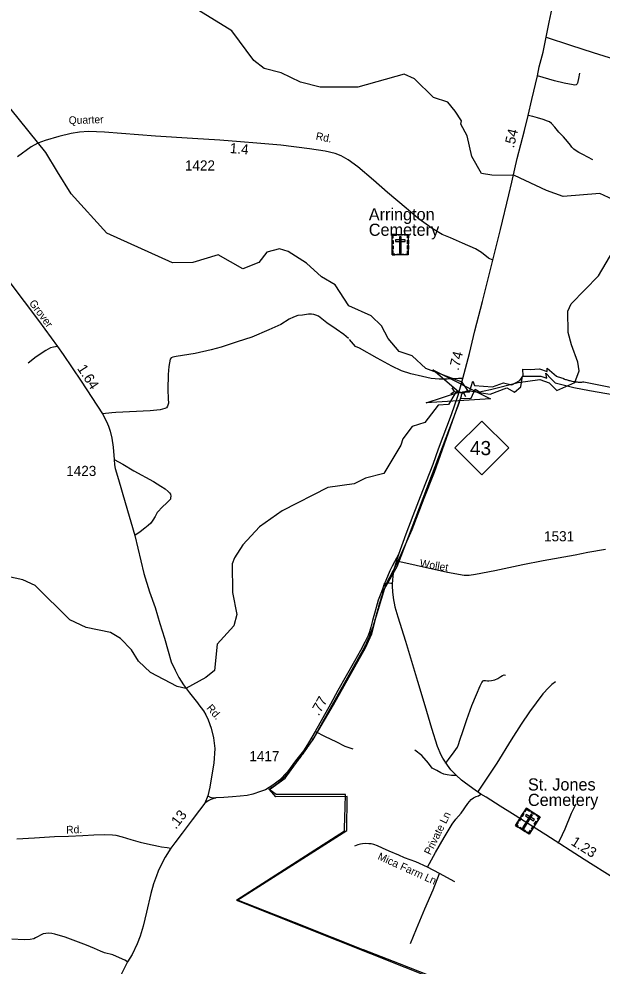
# Model space of a CAD drawing. Extents: x 2220236 to 2384410, y 720751 to 894131.
# Drawn here: x 2309628 to 2316835, y 842180 to 853889 of the extents above; entities that cross this region are included whole.
import ezdxf

# ---------------------------------------------------------------- set-up
doc = ezdxf.new("R2010")
doc.units = 0
doc.layers.add('Default', color=7, linetype='Continuous')

msp = doc.modelspace()

# ---------------------------------------------------------------- linework, layer by layer
at = {"layer": 'Default'}
for p, q in [((2314979, 849327), (2315007, 849285)), ((2314965, 849255), (2315007, 849285)), ((2315007, 849285), (2315125, 849261)), ((2315167, 849291), (2315125, 849261)), ((2315153, 849219), (2315125, 849261)), ((2314825, 843322), (2314676, 843403)), ((2315016, 843220), (2314825, 843322))]:
    msp.add_line(p, q, dxfattribs=at)
for points in [[(2316145, 853665), (2316183, 853850), (2316205, 853964), (2316226, 854081), (2316235, 854178), (2316238, 854273), (2316240, 854418), (2316238, 854579), (2316233, 854745), (2316224, 855064), (2316192, 855549), (2316193, 855755), (2316188, 855798)], [(2310106, 851999), (2309962, 852239), (2309531, 852769), (2309363, 852933), (2309057, 853505), (2308871, 853694), (2308704, 853819), (2308561, 853882), (2308119, 853913), (2308019, 853978), (2307934, 854066), (2307925, 854125), (2307799, 854284), (2307595, 854623), (2307342, 854918)], [(2317074, 851608), (2316806, 851732), (2316356, 851694), (2316147, 851767), (2315754, 851954), (2315471, 851959), (2315345, 851980), (2315227, 852189), (2315166, 852446), (2315089, 852587), (2315097, 852630), (2315021, 852751), (2314928, 852859), (2314752, 852918), (2314517, 853148), (2314391, 853205), (2313818, 853047), (2313352, 853044), (2313109, 853106), (2312867, 853221), (2312658, 853278), (2312532, 853375), (2312261, 853741), (2311850, 853994)], [(2315485, 850905), (2315579, 851285), (2315684, 851714), (2315720, 851871), (2315787, 852162), (2315877, 852509), (2315921, 852695), (2315969, 852895), (2316035, 853186), (2316059, 853297), (2316108, 853478), (2316145, 853665)], [(2316145, 853665), (2316445, 853567), (2316726, 853473), (2316988, 853393), (2317156, 853343), (2317317, 853308), (2317485, 853272), (2317630, 853225), (2317721, 853192), (2317809, 853152), (2317905, 853096), (2317993, 853031)], [(2316558, 853219), (2316543, 853154), (2316535, 853114), (2316530, 853096), (2316527, 853086), (2316522, 853081), (2316513, 853076), (2316498, 853069), (2316477, 853074), (2316367, 853097), (2316248, 853126), (2316108, 853167), (2316035, 853186)], [(2316722, 852147), (2316660, 852181), (2316597, 852214), (2316546, 852239), (2316514, 852260), (2316486, 852279), (2316463, 852305), (2316444, 852330), (2316406, 852375), (2316357, 852431), (2316302, 852491), (2316252, 852551), (2316210, 852596), (2316187, 852616), (2316162, 852626), (2316109, 852644), (2316035, 852667), (2315981, 852684), (2315921, 852695)], [(2315485, 850905), (2315431, 850932), (2315345, 851003), (2315272, 851048), (2315108, 851119), (2314961, 851181), (2314860, 851226), (2314734, 851297), (2314560, 851425), (2314415, 851549), (2314183, 851745), (2314012, 851898), (2313816, 852059), (2313697, 852147), (2313612, 852197), (2313537, 852225), (2313413, 852254), (2313219, 852285), (2312864, 852327), (2312567, 852353), (2312366, 852368), (2312109, 852390), (2311773, 852410), (2311316, 852441), (2310686, 852491), (2310489, 852496), (2310376, 852491), (2310273, 852471), (2310120, 852436), (2309953, 852387), (2309862, 852352), (2309779, 852307), (2309608, 852184)], [(2315177, 849296), (2315107, 849397), (2314655, 849566), (2314487, 849723), (2314328, 849779), (2314193, 849938), (2314108, 850095), (2313982, 850218), (2313705, 850341), (2313536, 850603), (2313368, 850701), (2313183, 850868), (2312957, 851016), (2312848, 851048), (2312690, 851005), (2312592, 850876), (2312393, 850799), (2312091, 850971), (2311776, 850876), (2311525, 850875), (2310714, 851239), (2310275, 851727), (2310106, 851999)], [(2315177, 849296), (2315300, 849275), (2315457, 849309), (2315798, 849396), (2316064, 849433), (2316181, 849392), (2316274, 849294), (2316498, 849395), (2316554, 849539), (2316537, 849646), (2316459, 849860), (2316416, 850012), (2316413, 850278), (2316454, 850368), (2316792, 850714), (2316980, 851033), (2317033, 851485), (2317074, 851608)], [(2314297, 847190), (2314325, 847272), (2314413, 847525), (2314502, 847751), (2314618, 848059), (2314746, 848384), (2314814, 848573), (2314976, 848997), (2315057, 849236), (2315113, 849442), (2315195, 849753), (2315264, 850033), (2315356, 850397), (2315485, 850905)], [(2309515, 850631), (2309868, 850159), (2310103, 849839), (2310174, 849742), (2310396, 849409), (2310660, 849007), (2310708, 848912), (2310734, 848856), (2310756, 848793), (2310777, 848708), (2310792, 848593), (2310804, 848442), (2310807, 848378), (2310817, 848332), (2310859, 848196), (2310940, 847909), (2311060, 847501), (2311170, 847034), (2311241, 846805), (2311312, 846614), (2311371, 846413), (2311425, 846235), (2311474, 846071), (2311509, 845941), (2311557, 845836), (2311604, 845747), (2311662, 845655), (2311735, 845557), (2311836, 845436), (2311852, 845410), (2311907, 845335), (2311937, 845287), (2311966, 845222), (2312003, 845122), (2312033, 845003), (2312049, 844871), (2312035, 844690), (2312007, 844518), (2311989, 844391), (2311962, 844285), (2311926, 844194)], [(2313703, 849937), (2313643, 849987), (2313547, 850055), (2313435, 850134), (2313331, 850213), (2313299, 850228), (2313273, 850236), (2313244, 850239), (2313205, 850239), (2313132, 850228), (2313074, 850221), (2313022, 850201), (2312969, 850178), (2312866, 850113), (2312717, 850045), (2312506, 849955), (2312325, 849897), (2312128, 849831), (2312004, 849799), (2311806, 849753), (2311651, 849729), (2311573, 849716), (2311530, 849706), (2311510, 849699), (2311498, 849683), (2311479, 849591), (2311472, 849492), (2311470, 849309), (2311474, 849193), (2311475, 849140), (2311464, 849103), (2311450, 849082), (2311430, 849072), (2311373, 849056), (2311249, 849046), (2310824, 849024), (2310774, 849019), (2310660, 849007)], [(2315113, 849442), (2315060, 849442), (2314979, 849439), (2314919, 849434), (2314823, 849434), (2314723, 849444), (2314614, 849469), (2314470, 849503), (2314357, 849540), (2314238, 849596), (2314055, 849694), (2313835, 849819), (2313786, 849839), (2313713, 849924)], [(2310103, 849839), (2310055, 849831), (2310019, 849823), (2309960, 849792), (2309839, 849711), (2309742, 849634)], [(2315200, 841864), (2314330, 842207), (2313887, 842382), (2313884, 842382), (2313500, 842534), (2313149, 842672), (2312320, 842999), (2313650, 843853), (2313650, 843882), (2313650, 843884), (2313659, 844145), (2313664, 844302), (2312980, 844300), (2312805, 844299), (2312716, 844366), (2312725, 844372), (2312735, 844378), (2312745, 844384), (2312755, 844390), (2312764, 844396), (2312774, 844403), (2312784, 844409), (2312793, 844416), (2312802, 844423), (2312812, 844430), (2312821, 844437), (2312830, 844444), (2312838, 844452), (2312847, 844459), (2312856, 844467), (2312864, 844475), (2312873, 844483), (2312881, 844491), (2312890, 844499), (2312898, 844508), (2312902, 844512), (2312906, 844516), (2312913, 844525), (2312921, 844533), (2312929, 844543), (2312937, 844552), (2312945, 844560), (2312952, 844569), (2312960, 844578), (2312968, 844586), (2312975, 844595), (2312983, 844604), (2312990, 844613), (2312998, 844622), (2313005, 844631), (2313012, 844640), (2313020, 844649), (2313027, 844658), (2313034, 844667), (2313042, 844676), (2313049, 844685), (2313056, 844694), (2313064, 844703), (2313070, 844712), (2313078, 844721), (2313085, 844730), (2313092, 844740), (2313099, 844749), (2313106, 844758), (2313113, 844767), (2313120, 844777), (2313126, 844786), (2313134, 844795), (2313140, 844805), (2313147, 844814), (2313154, 844824), (2313160, 844833), (2313167, 844842), (2313174, 844852), (2313180, 844862), (2313187, 844871), (2313194, 844881), (2313200, 844890), (2313207, 844900), (2313213, 844909), (2313216, 844914), (2313220, 844919), (2313226, 844929), (2313232, 844938), (2313239, 844948), (2313245, 844958), (2313251, 844968), (2313258, 844978), (2313264, 844987), (2313270, 844997), (2313276, 845007), (2313282, 845017), (2313288, 845027), (2313294, 845037), (2313300, 845047), (2313306, 845057), (2313312, 845067), (2313318, 845077), (2313327, 845094), (2313882, 846088), (2313887, 846098), (2313892, 846108), (2313898, 846119), (2313903, 846130), (2313908, 846140), (2313913, 846150), (2313918, 846160), (2313923, 846171), (2313928, 846182), (2313932, 846192), (2313937, 846203), (2313942, 846213), (2313946, 846223), (2313946, 846224), (2313951, 846234), (2313956, 846245), (2313960, 846256), (2313968, 846277), (2313973, 846288), (2313977, 846299), (2313981, 846310), (2313985, 846321), (2313989, 846332), (2313993, 846343), (2313997, 846354), (2314001, 846364), (2314005, 846375), (2314008, 846386), (2314012, 846397), (2314016, 846408), (2314019, 846420), (2314022, 846431), (2314026, 846442), (2314032, 846464), (2314036, 846475), (2314039, 846486), (2314042, 846497), (2314045, 846509), (2314048, 846520), (2314053, 846540), (2314056, 846551), (2314058, 846562), (2314062, 846574), (2314064, 846585), (2314068, 846596), (2314070, 846607), (2314074, 846618), (2314077, 846630), (2314080, 846641), (2314083, 846652), (2314086, 846663), (2314096, 846696), (2314100, 846708), (2314103, 846719), (2314106, 846730), (2314110, 846741), (2314113, 846752), (2314116, 846763), (2314120, 846774), (2314124, 846785), (2314127, 846796), (2314130, 846807), (2314134, 846818), (2314138, 846829), (2314144, 846842), (2314303, 847119), (2314352, 847247), (2314999, 848954), (2315003, 848965), (2315008, 848976), (2315012, 848987), (2315016, 848997), (2315020, 849008), (2315024, 849019), (2315028, 849030), (2315032, 849041), (2315036, 849052), (2315040, 849063), (2315044, 849074), (2315048, 849084), (2315052, 849095), (2315056, 849106), (2315060, 849117), (2315071, 849150), (2315074, 849161), (2315078, 849172), (2315082, 849183), (2315085, 849194), (2315089, 849205), (2315092, 849216), (2315096, 849228), (2315099, 849239), (2315109, 849272), (2315110, 849277), (2315195, 849277), (2315238, 849409), (2315258, 849358), (2315481, 849341), (2315616, 849392), (2315720, 849367), (2315819, 849419), (2315858, 849476), (2315856, 849559), (2315946, 849557), (2316061, 849563), (2316158, 849531), (2316158, 849571), (2316270, 849472), (2316282, 849468), (2316361, 849442), (2316359, 849440), (2316382, 849433), (2316393, 849430), (2316404, 849427), (2316415, 849424), (2316426, 849420), (2316438, 849418), (2316449, 849415), (2316460, 849412), (2316482, 849407), (2316494, 849405), (2316506, 849403), (2316517, 849402), (2316528, 849401), (2316540, 849400), (2316552, 849399), (2316563, 849399), (2316575, 849399), (2316586, 849400), (2316598, 849401), (2316610, 849402), (2316611, 849402), (2317727, 849181)], [(2315200, 841864), (2314330, 842207), (2313887, 842382), (2313884, 842382), (2313500, 842534), (2313149, 842672), (2312320, 842999), (2313650, 843853), (2313650, 843882), (2313650, 843884), (2313659, 844145), (2313664, 844302), (2312980, 844300), (2312805, 844299), (2312716, 844366), (2312725, 844372), (2312735, 844378), (2312745, 844384), (2312755, 844390), (2312764, 844396), (2312774, 844403), (2312784, 844409), (2312793, 844416), (2312802, 844423), (2312812, 844430), (2312821, 844437), (2312830, 844444), (2312838, 844452), (2312847, 844459), (2312856, 844467), (2312864, 844475), (2312873, 844483), (2312881, 844491), (2312890, 844499), (2312898, 844508), (2312902, 844512), (2312906, 844516), (2312913, 844525), (2312921, 844533), (2312929, 844543), (2312937, 844552), (2312945, 844560), (2312952, 844569), (2312960, 844578), (2312968, 844586), (2312975, 844595), (2312983, 844604), (2312990, 844613), (2312998, 844622), (2313005, 844631), (2313012, 844640), (2313020, 844649), (2313027, 844658), (2313034, 844667), (2313042, 844676), (2313049, 844685), (2313056, 844694), (2313064, 844703), (2313070, 844712), (2313078, 844721), (2313085, 844730), (2313092, 844740), (2313099, 844749), (2313106, 844758), (2313113, 844767), (2313120, 844777), (2313126, 844786), (2313134, 844795), (2313140, 844805), (2313147, 844814), (2313154, 844824), (2313160, 844833), (2313167, 844842), (2313174, 844852), (2313180, 844862), (2313187, 844871), (2313194, 844881), (2313200, 844890), (2313207, 844900), (2313213, 844909), (2313216, 844914), (2313220, 844919), (2313226, 844929), (2313232, 844938), (2313239, 844948), (2313245, 844958), (2313251, 844968), (2313258, 844978), (2313264, 844987), (2313270, 844997), (2313276, 845007), (2313282, 845017), (2313288, 845027), (2313294, 845037), (2313300, 845047), (2313306, 845057), (2313312, 845067), (2313318, 845077), (2313327, 845094), (2313882, 846088), (2313887, 846098), (2313892, 846108), (2313898, 846119), (2313903, 846130), (2313908, 846140), (2313913, 846150), (2313918, 846160), (2313923, 846171), (2313928, 846182), (2313932, 846192), (2313937, 846203), (2313942, 846213), (2313946, 846223), (2313946, 846224), (2313951, 846234), (2313956, 846245), (2313960, 846256), (2313968, 846277), (2313973, 846288), (2313977, 846299), (2313981, 846310), (2313985, 846321), (2313989, 846332), (2313993, 846343), (2313997, 846354), (2314001, 846364), (2314005, 846375), (2314008, 846386), (2314012, 846397), (2314016, 846408), (2314019, 846420), (2314022, 846431), (2314026, 846442), (2314032, 846464), (2314036, 846475), (2314039, 846486), (2314042, 846497), (2314045, 846509), (2314048, 846520), (2314053, 846540), (2314056, 846551), (2314058, 846562), (2314062, 846574), (2314064, 846585), (2314068, 846596), (2314070, 846607), (2314074, 846618), (2314077, 846630), (2314080, 846641), (2314083, 846652), (2314086, 846663), (2314096, 846696), (2314100, 846708), (2314103, 846719), (2314106, 846730), (2314110, 846741), (2314113, 846752), (2314116, 846763), (2314120, 846774), (2314124, 846785), (2314127, 846796), (2314130, 846807), (2314134, 846818), (2314138, 846829), (2314144, 846842), (2314303, 847119), (2314352, 847247), (2314999, 848954), (2315003, 848965), (2315008, 848976), (2315012, 848987), (2315016, 848997), (2315020, 849008), (2315024, 849019), (2315028, 849030), (2315032, 849041), (2315036, 849052), (2315040, 849063), (2315044, 849074), (2315048, 849084), (2315052, 849095), (2315056, 849106), (2315060, 849117), (2315071, 849150), (2315074, 849161), (2315078, 849172), (2315082, 849183), (2315085, 849194), (2315089, 849205), (2315092, 849216), (2315096, 849228), (2315099, 849239), (2315109, 849272), (2315110, 849277), (2315195, 849277), (2315238, 849409), (2315258, 849358), (2315481, 849341), (2315616, 849392), (2315720, 849367), (2315819, 849419), (2315858, 849476), (2315856, 849559), (2315946, 849557), (2316061, 849563), (2316158, 849531), (2316158, 849571), (2316270, 849472), (2316282, 849468), (2316361, 849442), (2316359, 849440), (2316382, 849433), (2316393, 849430), (2316404, 849427), (2316415, 849424), (2316426, 849420), (2316438, 849418), (2316449, 849415), (2316460, 849412), (2316482, 849407), (2316494, 849405), (2316506, 849403), (2316517, 849402), (2316528, 849401), (2316540, 849400), (2316552, 849399), (2316563, 849399), (2316575, 849399), (2316586, 849400), (2316598, 849401), (2316610, 849402), (2316611, 849402), (2317727, 849181)], [(2315228, 841831), (2312322, 842991), (2313681, 843857), (2313686, 844275), (2312802, 844270), (2312725, 844363), (2312917, 844503), (2312994, 844607), (2313263, 844981), (2313516, 845410), (2313912, 846113), (2313988, 846289), (2314043, 846498), (2314163, 846891), (2314306, 847171), (2314487, 847578), (2314636, 847963), (2314762, 848287), (2315086, 849197), (2315218, 849202), (2315267, 849312), (2315339, 849268), (2315454, 849252), (2315657, 849329), (2315751, 849274), (2315833, 849340), (2315850, 849471), (2316080, 849471), (2316152, 849449), (2316141, 849510), (2316207, 849438), (2316256, 849389), (2316487, 849334), (2316679, 849296), (2317747, 849109)], [(2315177, 849296), (2315115, 849265), (2315066, 849273), (2315042, 849277), (2315027, 849271), (2315014, 849255), (2314938, 849124), (2314811, 849113), (2314646, 848899), (2314488, 848850), (2314373, 848698), (2314349, 848621), (2314136, 848271), (2313912, 848210), (2313771, 848141), (2313446, 848095), (2312883, 847806), (2312602, 847611), (2312396, 847386), (2312290, 847227), (2312265, 847151), (2312269, 846800), (2312322, 846526), (2312282, 846384), (2312076, 846159), (2312046, 845832), (2311939, 845749), (2311691, 845611), (2311582, 845636), (2311255, 845807), (2311104, 845948), (2311019, 846089), (2310884, 846228), (2310758, 846302), (2310458, 846365), (2310257, 846462), (2309828, 846884), (2309677, 846956), (2309485, 846994)], [(2310804, 848442), (2310913, 848383), (2311047, 848302), (2311289, 848171), (2311381, 848114), (2311434, 848078), (2311474, 848047), (2311488, 848031), (2311500, 848013), (2311505, 847989), (2311503, 847969), (2311499, 847951), (2311473, 847923), (2311446, 847899), (2311406, 847860), (2311337, 847788), (2311311, 847737), (2311282, 847691), (2311256, 847655), (2311225, 847627), (2311185, 847594), (2311128, 847549), (2311060, 847501)], [(2314297, 847190), (2314539, 847135), (2314926, 847051), (2315130, 847013), (2315191, 847013), (2315269, 847023), (2315509, 847070), (2315855, 847145), (2316109, 847193), (2316502, 847264), (2316660, 847295), (2316877, 847333)], [(2314138, 846884), (2314165, 846949), (2314218, 847070), (2314243, 847127), (2314275, 847181), (2314299, 847228), (2314325, 847272)], [(2314244, 846910), (2314250, 846947), (2314254, 847004), (2314267, 847085), (2314297, 847190)], [(2314244, 846910), (2314204, 846912), (2314184, 846914), (2314155, 846901), (2314138, 846884), (2314130, 846866), (2314108, 846806), (2314067, 846702), (2314032, 846567), (2313999, 846451), (2313976, 846370), (2313962, 846313), (2313943, 846265), (2313903, 846184), (2313849, 846081), (2313776, 845951), (2313570, 845588), (2313478, 845416), (2313287, 845080), (2313207, 844941), (2313144, 844840), (2313046, 844715), (2312949, 844581), (2312848, 844478), (2312765, 844415), (2312675, 844360), (2312613, 844338), (2312518, 844305), (2312447, 844290), (2312361, 844282), (2312269, 844273), (2312162, 844264), (2312062, 844258), (2311998, 844237), (2311967, 844223), (2311926, 844194)], [(2314139, 846908), (2314174, 846915), (2314190, 846917), (2314205, 846916), (2314225, 846912), (2314243, 846907)], [(2316979, 843267), (2316613, 843499), (2316141, 843800), (2315730, 844060), (2315576, 844156), (2315401, 844267), (2315337, 844304), (2315267, 844356), (2315149, 844440), (2315098, 844479), (2315030, 844540), (2314966, 844606), (2314924, 844665), (2314899, 844700), (2314868, 844748), (2314848, 844786), (2314802, 844893), (2314731, 845117), (2314647, 845398), (2314556, 845697), (2314408, 846191), (2314314, 846495), (2314279, 846617), (2314273, 846647), (2314260, 846708), (2314250, 846803), (2314245, 846880), (2314244, 846910)], [(2314901, 844684), (2314937, 844732), (2315006, 844827), (2315047, 844886), (2315062, 844920), (2315079, 844971), (2315117, 845091), (2315165, 845227), (2315225, 845403), (2315284, 845536), (2315329, 845645), (2315349, 845685), (2315364, 845707), (2315374, 845712), (2315394, 845710), (2315419, 845707), (2315434, 845707), (2315469, 845710), (2315508, 845718), (2315548, 845735), (2315583, 845758), (2315606, 845773), (2315625, 845780), (2315641, 845778)], [(2316260, 845694), (2316216, 845662), (2316177, 845625), (2316105, 845547), (2316022, 845433), (2315937, 845322), (2315835, 845169), (2315710, 844975), (2315535, 844689), (2315295, 844328)], [(2313759, 844863), (2313661, 844893), (2313548, 844953), (2313417, 845015), (2313287, 845080)], [(2315027, 844535), (2314974, 844535), (2314922, 844542), (2314881, 844552), (2314843, 844570), (2314792, 844596), (2314737, 844627), (2314690, 844686), (2314606, 844783), (2314521, 844848)], [(2311962, 844285), (2311993, 844269), (2312021, 844261), (2312062, 844258)], [(2314676, 843403), (2314778, 843584), (2314884, 843768), (2314981, 843933), (2315028, 843994), (2315093, 844069), (2315178, 844191), (2315218, 844237), (2315244, 844259), (2315281, 844276), (2315309, 844286), (2315337, 844304)], [(2311926, 844194), (2311861, 844108), (2311770, 843986), (2311644, 843823), (2311553, 843703), (2311504, 843637)], [(2316510, 844183), (2316453, 844066), (2316375, 843871), (2316310, 843733), (2316289, 843694)], [(2309600, 843754), (2309818, 843766), (2310068, 843782), (2310242, 843786), (2310416, 843792), (2310552, 843800), (2310689, 843806), (2310783, 843802), (2310826, 843796), (2310904, 843779), (2311011, 843746), (2311125, 843713), (2311215, 843691), (2311351, 843661), (2311391, 843655), (2311458, 843645), (2311504, 843637)], [(2314676, 843403), (2314534, 843470), (2314393, 843518), (2314322, 843552), (2314204, 843600), (2314121, 843639), (2314061, 843664), (2314013, 843681), (2313981, 843689), (2313954, 843691), (2313913, 843693), (2313875, 843692), (2313848, 843685), (2313817, 843677), (2313777, 843660)], [(2311504, 843637), (2311437, 843527), (2311390, 843441), (2311347, 843352), (2311326, 843296), (2311291, 843195), (2311257, 843075), (2311204, 842845), (2311163, 842674), (2311126, 842549), (2311089, 842456), (2311026, 842321), (2310968, 842231), (2310873, 842044)], [(2314466, 842458), (2314542, 842638), (2314644, 842885), (2314746, 843123), (2314825, 843322)], [(2310968, 842231), (2310935, 842251), (2310872, 842283), (2310788, 842318), (2310684, 842345), (2310634, 842362), (2310563, 842395), (2310463, 842438), (2310332, 842489), (2310198, 842535), (2310072, 842572), (2310033, 842582), (2309995, 842587), (2309962, 842583), (2309928, 842576), (2309834, 842527), (2309810, 842517), (2309768, 842507), (2309691, 842504), (2309540, 842510)]]:
    msp.add_lwpolyline(points, dxfattribs=at)
for points in [[(2314241, 851226), (2314440, 851226), (2314440, 850971), (2314241, 850971)], [(2314241, 851182), (2314253, 851182), (2314253, 851215), (2314293, 851215), (2314293, 851226), (2314241, 851226)], [(2314315, 851226), (2314367, 851226), (2314367, 851214), (2314315, 851214)], [(2314350, 851196), (2314332, 851196), (2314332, 850994), (2314350, 850994)], [(2314441, 851182), (2314429, 851182), (2314429, 851215), (2314389, 851215), (2314389, 851226), (2314441, 851226)], [(2314241, 851108), (2314241, 851152), (2314253, 851152), (2314253, 851108)], [(2314241, 851041), (2314241, 851084), (2314253, 851084), (2314253, 851041)], [(2314282, 851158), (2314282, 851139), (2314400, 851139), (2314400, 851158)], [(2314429, 851109), (2314429, 851153), (2314441, 851153), (2314441, 851109)], [(2314429, 851043), (2314429, 851087), (2314441, 851087), (2314441, 851043)], [(2314274, 850971), (2314274, 850983), (2314252, 850983), (2314252, 851023), (2314241, 851023), (2314241, 850971)], [(2314299, 850983), (2314384, 850983), (2314384, 850971), (2314299, 850971)], [(2314407, 850971), (2314407, 850983), (2314429, 850983), (2314429, 851023), (2314440, 851023), (2314440, 850971)], [(2314742, 849550), (2315458, 849193), (2314660, 849144), (2315066, 849273)], [(2315016, 848585), (2315349, 848918), (2315682, 848585), (2315349, 848252)], [(2315900, 844132), (2316068, 844026), (2315933, 843810), (2315764, 843916)], [(2315837, 844032), (2315860, 844069), (2315870, 844063), (2315847, 844026)], [(2315976, 844049), (2315960, 844059), (2315853, 843887), (2315869, 843877)], [(2315877, 844095), (2315886, 844089), (2315903, 844116), (2315938, 844095), (2315943, 844104), (2315900, 844132)], [(2315898, 844052), (2315888, 844037), (2315988, 843974), (2315998, 843990)], [(2315962, 844092), (2316006, 844065), (2316000, 844055), (2315956, 844083)], [(2316045, 843989), (2316036, 843995), (2316053, 844022), (2316018, 844044), (2316024, 844053), (2316068, 844026)], [(2315792, 843898), (2315798, 843908), (2315780, 843920), (2315801, 843954), (2315792, 843960), (2315764, 843916)], [(2315801, 843975), (2315824, 844012), (2315834, 844006), (2315811, 843969)], [(2315997, 843933), (2316020, 843970), (2316029, 843964), (2316006, 843927)], [(2315819, 843895), (2315891, 843850), (2315885, 843840), (2315813, 843886)], [(2315905, 843828), (2315911, 843838), (2315930, 843826), (2315951, 843860), (2315960, 843854), (2315933, 843810)], [(2315962, 843877), (2315985, 843914), (2315994, 843908), (2315971, 843871)]]:
    msp.add_lwpolyline(points, close=True, dxfattribs=at)

# ---------------------------------------------------------------- texts
for s, height, rotation, p in [('Quarter', 95, 1.6184, (2310244, 852589)), ('Rd.', 95, 348.9522, (2313291, 852398)), ('.54', 125, 76.3072, (2315744, 852287)), ('1.4', 125, 355.2152, (2312230, 852232)), ('Grover', 95, 306.7728, (2309748, 850374)), ('.74', 125, 76.034, (2315062, 849536)), ('1.64', 125, 303.0965, (2310343, 849568)), ('Wollet', 95, 350.6083, (2314577, 847117)), ('.77', 125, 60.1099, (2313332, 845265)), ('Rd.', 95, 310.7982, (2311940, 845366)), ('.13', 125, 51.9912, (2311568, 843864)), ('Private Ln', 95, 63.6673, (2314715, 843545)), ('Rd.', 95, 2.0763, (2310213, 843817)), ('1.23', 125, 327.9071, (2316441, 843686)), ('Mica Farm Ln', 95, 335.7621, (2314053, 843502))]:
    msp.add_text(s, height=height, rotation=rotation, dxfattribs=at).set_placement(p)
for s, height, p in [('1422', 125, (2311679, 852015)), ('Arrington', 150, (2313952, 851399)), ('Cemetery', 150, (2313952, 851208)), ('43', 175, (2315203, 848496)), ('1423', 125, (2310212, 848239)), ('1531', 125, (2316118, 847431)), ('1417', 125, (2312475, 844712)), ('St. Jones', 150, (2315919, 844350)), ('Cemetery', 150, (2315919, 844159))]:
    msp.add_text(s, height=height, dxfattribs=at).set_placement(p)

doc.saveas('drawing.dxf')
